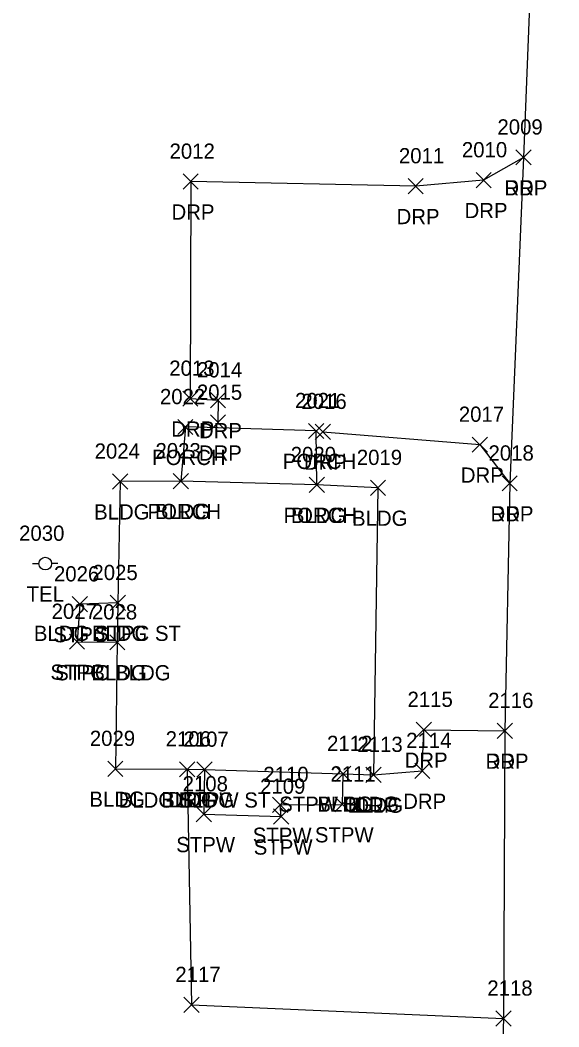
# Model space of a CAD drawing. Extents: x 1767353 to 1772625, y 740790 to 747702.
# Drawn here: x 1770195.4 to 1770266.1, y 741538.9 to 741671.2 of the extents above; entities that cross this region are included whole.
import ezdxf

# ---------------------------------------------------------------- set-up
doc = ezdxf.new("R2010")
doc.units = 0
for name, color, linetype in [('L_A', 7, 'Continuous'), ('L_I', 7, 'Continuous'), ('L_TIC', 7, 'Continuous'), ('LBC', 7, 'Continuous'), ('LBF', 7, 'Continuous'), ('P_A', 7, 'Continuous'), ('P_I', 7, 'Continuous'), ('P_TIC', 7, 'Continuous'), ('PET', 7, 'Continuous'), ('R_A', 7, 'Continuous'), ('R_I', 7, 'Continuous'), ('R_TIC', 7, 'Continuous'), ('RDP', 7, 'Continuous'), ('U_A', 7, 'Continuous'), ('U_I', 7, 'Continuous'), ('UP', 7, 'Continuous')]:
    doc.layers.add(name, color=color, linetype=linetype)

msp = doc.modelspace()

# ---------------------------------------------------------------- linework, layer by layer
at = {"layer": 'L_TIC'}
for points in [[(1770216.09, 741616.75), (1770218.09, 741618.75)], [(1770218.09, 741616.75), (1770216.09, 741618.75)], [(1770233.26, 741616.23), (1770235.26, 741618.23)], [(1770235.26, 741616.23), (1770233.26, 741618.23)], [(1770207.51, 741609.59), (1770209.51, 741611.59)], [(1770209.51, 741609.59), (1770207.51, 741611.59)], [(1770215.5, 741609.64), (1770217.5, 741611.64)], [(1770217.5, 741609.64), (1770215.5, 741611.64)], [(1770215.5, 741609.64), (1770217.5, 741611.64)], [(1770217.5, 741609.64), (1770215.5, 741611.64)], [(1770233.35, 741609.14), (1770235.35, 741611.14)], [(1770235.35, 741609.14), (1770233.35, 741611.14)], [(1770233.35, 741609.14), (1770235.35, 741611.14)], [(1770235.35, 741609.14), (1770233.35, 741611.14)], [(1770241.39, 741608.76), (1770243.39, 741610.76)], [(1770243.39, 741608.76), (1770241.39, 741610.76)], [(1770241.39, 741608.76), (1770243.39, 741610.76)], [(1770243.39, 741608.76), (1770241.39, 741610.76)], [(1770202.22, 741593.45), (1770204.22, 741595.45)], [(1770204.22, 741593.45), (1770202.22, 741595.45)], [(1770207.22, 741593.63), (1770209.22, 741595.63)], [(1770209.22, 741593.63), (1770207.22, 741595.63)], [(1770207.22, 741593.63), (1770209.22, 741595.63)], [(1770209.22, 741593.63), (1770207.22, 741595.63)], [(1770201.86, 741588.53), (1770203.86, 741590.53)], [(1770203.86, 741588.53), (1770201.86, 741590.53)], [(1770207.15, 741588.45), (1770209.15, 741590.45)], [(1770209.15, 741588.45), (1770207.15, 741590.45)], [(1770207.15, 741588.45), (1770209.15, 741590.45)], [(1770209.15, 741588.45), (1770207.15, 741590.45)], [(1770206.89, 741571.83), (1770208.89, 741573.83)], [(1770208.89, 741571.83), (1770206.89, 741573.83)], [(1770216.33, 741571.76), (1770218.33, 741573.76)], [(1770218.33, 741571.76), (1770216.33, 741573.76)], [(1770218.61, 741571.72), (1770220.61, 741573.72)], [(1770220.61, 741571.72), (1770218.61, 741573.72)], [(1770218.61, 741571.72), (1770220.61, 741573.72)], [(1770220.61, 741571.72), (1770218.61, 741573.72)], [(1770236.83, 741571.17), (1770238.83, 741573.17)], [(1770238.83, 741571.17), (1770236.83, 741573.17)], [(1770236.83, 741571.17), (1770238.83, 741573.17)], [(1770238.83, 741571.17), (1770236.83, 741573.17)], [(1770240.81, 741571.04), (1770242.81, 741573.04)], [(1770242.81, 741571.04), (1770240.81, 741573.04)], [(1770240.81, 741571.04), (1770242.81, 741573.04)], [(1770242.81, 741571.04), (1770240.81, 741573.04)], [(1770218.5, 741565.86), (1770220.5, 741567.86)], [(1770220.5, 741565.86), (1770218.5, 741567.86)], [(1770228.54, 741567.09), (1770230.54, 741569.09)], [(1770230.54, 741567.09), (1770228.54, 741569.09)], [(1770236.71, 741567.15), (1770238.71, 741569.15)], [(1770238.71, 741567.15), (1770236.71, 741569.15)], [(1770228.68, 741565.54), (1770230.68, 741567.54)], [(1770230.68, 741565.54), (1770228.68, 741567.54)]]:
    msp.add_lwpolyline(points, dxfattribs=at)
at = {"layer": 'LBC'}
for points in [[(1770242.39, 741609.76), (1770234.35, 741610.14), (1770216.5, 741610.64), (1770208.51, 741610.59), (1770208.22, 741594.63), (1770208.15, 741589.45), (1770207.89, 741572.83), (1770217.33, 741572.76), (1770219.61, 741572.72), (1770237.83, 741572.17), (1770241.81, 741572.04)], [(1770242.39, 741609.76), (1770241.81, 741572.04)]]:
    msp.add_lwpolyline(points, dxfattribs=at)
at = {"layer": 'LBF'}
for points in [[(1770234.35, 741610.14), (1770234.26, 741617.23), (1770217.09, 741617.75), (1770216.5, 741610.64)], [(1770208.22, 741594.63), (1770203.22, 741594.45), (1770202.86, 741589.53), (1770208.15, 741589.45)], [(1770219.61, 741572.72), (1770219.5, 741566.86), (1770229.68, 741566.54), (1770229.54, 741568.09), (1770237.71, 741568.15), (1770237.83, 741572.17)]]:
    msp.add_lwpolyline(points, dxfattribs=at)
at = {"layer": 'P_TIC'}
for points in [[(1770260.51, 741652.19), (1770262.51, 741654.19)], [(1770262.51, 741652.19), (1770260.51, 741654.19)], [(1770258.69, 741609.34), (1770260.69, 741611.34)], [(1770260.69, 741609.34), (1770258.69, 741611.34)], [(1770258.69, 741609.34), (1770260.69, 741611.34)], [(1770260.69, 741609.34), (1770258.69, 741611.34)], [(1770258.04, 741576.82), (1770260.04, 741578.82)], [(1770260.04, 741576.82), (1770258.04, 741578.82)], [(1770257.88, 741539.01), (1770259.88, 741541.01)], [(1770259.88, 741539.01), (1770257.88, 741541.01)]]:
    msp.add_lwpolyline(points, dxfattribs=at)
at = {"layer": 'PET'}
for points in [[(1770229.78, 741893.6), (1770250.07, 741887.1), (1770256.68, 741881.35), (1770263.49, 741873.94), (1770265.43, 741863.52), (1770266.15, 741845.69), (1770265.98, 741804.45), (1770264.31, 741748.35), (1770263.25, 741697.67), (1770261.51, 741653.19), (1770259.69, 741610.34)], [(1770259.69, 741610.34), (1770259.04, 741577.82), (1770258.88, 741540.01), (1770257.94, 741510.97), (1770256.82, 741408.89)]]:
    msp.add_lwpolyline(points, dxfattribs=at)
at = {"layer": 'R_TIC'}
for points in [[(1770260.51, 741652.19), (1770262.51, 741654.19)], [(1770262.51, 741652.19), (1770260.51, 741654.19)], [(1770216.79, 741649.01), (1770218.79, 741651.01)], [(1770218.79, 741649.01), (1770216.79, 741651.01)], [(1770246.34, 741648.41), (1770248.34, 741650.41)], [(1770248.34, 741648.41), (1770246.34, 741650.41)], [(1770255.27, 741649.2), (1770257.27, 741651.2)], [(1770257.27, 741649.2), (1770255.27, 741651.2)], [(1770216.74, 741620.48), (1770218.74, 741622.48)], [(1770218.74, 741620.48), (1770216.74, 741622.48)], [(1770220.38, 741620.27), (1770222.38, 741622.27)], [(1770222.38, 741620.27), (1770220.38, 741622.27)], [(1770220.37, 741617.33), (1770222.37, 741619.33)], [(1770222.37, 741617.33), (1770220.37, 741619.33)], [(1770234.16, 741616.12), (1770236.16, 741618.12)], [(1770236.16, 741616.12), (1770234.16, 741618.12)], [(1770254.78, 741614.43), (1770256.78, 741616.43)], [(1770256.78, 741614.43), (1770254.78, 741616.43)], [(1770258.69, 741609.34), (1770260.69, 741611.34)], [(1770260.69, 741609.34), (1770258.69, 741611.34)], [(1770247.4, 741576.96), (1770249.4, 741578.96)], [(1770249.4, 741576.96), (1770247.4, 741578.96)], [(1770258.04, 741576.82), (1770260.04, 741578.82)], [(1770260.04, 741576.82), (1770258.04, 741578.82)], [(1770216.33, 741571.76), (1770218.33, 741573.76)], [(1770218.33, 741571.76), (1770216.33, 741573.76)], [(1770247.21, 741571.56), (1770249.21, 741573.56)], [(1770249.21, 741571.56), (1770247.21, 741573.56)], [(1770240.81, 741571.04), (1770242.81, 741573.04)], [(1770242.81, 741571.04), (1770240.81, 741573.04)], [(1770216.9, 741540.8), (1770218.9, 741542.8)], [(1770218.9, 741540.8), (1770216.9, 741542.8)], [(1770257.88, 741539.01), (1770259.88, 741541.01)], [(1770259.88, 741539.01), (1770257.88, 741541.01)]]:
    msp.add_lwpolyline(points, dxfattribs=at)
at = {"layer": 'RDP'}
for points in [[(1770261.51, 741653.19), (1770256.27, 741650.2), (1770247.34, 741649.41), (1770217.79, 741650.01), (1770217.74, 741621.48), (1770221.38, 741621.27), (1770221.37, 741618.33)], [(1770235.16, 741617.12), (1770255.78, 741615.43), (1770259.69, 741610.34)], [(1770241.81, 741572.04), (1770248.21, 741572.56), (1770248.4, 741577.96), (1770259.04, 741577.82)], [(1770217.33, 741572.76), (1770217.9, 741541.8), (1770258.88, 741540.01)]]:
    msp.add_lwpolyline(points, dxfattribs=at)
at = {"layer": 'UP'}
for p, q in [((1770197.02, 741599.79), (1770197.84, 741599.79)), ((1770198.68, 741599.79), (1770198.68, 741599.79)), ((1770200.34, 741599.79), (1770199.51, 741599.79)), ((1770199.51, 741599.79), (1770199.51, 741599.79)), ((1770200.34, 741599.79), (1770200.34, 741599.79))]:
    msp.add_line(p, q, dxfattribs=at)
msp.add_circle((1770198.68, 741599.79), 0.833, dxfattribs=at)

# ---------------------------------------------------------------- texts
at = {"layer": 'L_A'}
for s, p in [('PORCH', (1770212.72, 741612.75)), ('PORCH', (1770229.88, 741612.23)), ('BLDG', (1770205.1, 741605.59)), ('PORCH', (1770212.12, 741605.64)), ('BLDG', (1770213.09, 741605.64)), ('PORCH', (1770229.98, 741605.14)), ('BLDG', (1770230.95, 741605.14)), ('BLDG', (1770238.98, 741604.76)), ('BLDG', (1770238.98, 741604.76)), ('BLDG STPC ST', (1770197.19, 741589.63)), ('STPC', (1770199.74, 741589.45)), ('BLDG', (1770204.81, 741589.63)), ('STPC', (1770199.37, 741584.53)), ('STPC BLDG', (1770199.99, 741584.45)), ('BLDG', (1770204.74, 741584.45)), ('BLDG', (1770204.48, 741567.83)), ('BLDG STPW ST', (1770208.33, 741567.72)), ('BLDG', (1770213.92, 741567.76)), ('BLDG', (1770216.2, 741567.72)), ('STPW BLDG', (1770229.41, 741567.17)), ('BLDG', (1770234.42, 741567.17)), ('BLDG', (1770238.4, 741567.04)), ('BLDG', (1770238.4, 741567.04)), ('STPW', (1770215.89, 741561.86)), ('STPW', (1770225.94, 741563.09)), ('STPW', (1770234.1, 741563.15)), ('STPW', (1770226.07, 741561.54))]:
    msp.add_text(s, height=2, dxfattribs=at).set_placement(p)
at = {"layer": 'L_I'}
for s, p in [('2022', (1770213.75, 741620.75)), ('2021', (1770231.49, 741620.23)), ('2024', (1770205.17, 741613.59)), ('2023', (1770213.16, 741613.64)), ('2023', (1770213.16, 741613.64)), ('2020', (1770230.93, 741613.14)), ('2020', (1770230.93, 741613.14)), ('2019', (1770239.61, 741612.76)), ('2019', (1770239.61, 741612.76)), ('2025', (1770204.88, 741597.63)), ('2025', (1770204.88, 741597.63)), ('2026', (1770199.83, 741597.45)), ('2027', (1770199.52, 741592.53)), ('2028', (1770204.81, 741592.45)), ('2028', (1770204.81, 741592.45)), ('2029', (1770204.54, 741575.83)), ('2106', (1770214.5, 741575.76)), ('2107', (1770216.84, 741575.72)), ('2107', (1770216.84, 741575.72)), ('2112', (1770235.7, 741575.17)), ('2112', (1770235.7, 741575.17)), ('2113', (1770239.69, 741575.04)), ('2113', (1770239.69, 741575.04)), ('2111', (1770236.15, 741571.15)), ('2108', (1770216.73, 741569.86)), ('2110', (1770227.33, 741571.09)), ('2109', (1770226.9, 741569.54))]:
    msp.add_text(s, height=2, dxfattribs=at).set_placement(p)
at = {"layer": 'P_A'}
for p in [(1770258.99, 741648.19), (1770257.17, 741605.34), (1770257.17, 741605.34), (1770256.52, 741572.82)]:
    msp.add_text('RDP', height=2, dxfattribs=at).set_placement(p)
at = {"layer": 'P_I'}
for s, p in [('2009', (1770258.08, 741656.19)), ('2018', (1770256.91, 741613.34)), ('2018', (1770256.91, 741613.34)), ('2116', (1770256.86, 741580.82)), ('2118', (1770256.75, 741543.01))]:
    msp.add_text(s, height=2, dxfattribs=at).set_placement(p)
at = {"layer": 'R_A'}
for p in [(1770258.99, 741648.19), (1770215.27, 741645.01), (1770244.83, 741644.41), (1770253.76, 741645.2), (1770215.23, 741616.48), (1770218.87, 741616.27), (1770218.86, 741613.33), (1770232.65, 741612.12), (1770253.27, 741610.43), (1770257.17, 741605.34), (1770245.89, 741572.96), (1770256.52, 741572.82), (1770214.81, 741567.76), (1770245.7, 741567.56), (1770239.3, 741567.04)]:
    msp.add_text('DRP', height=2, dxfattribs=at).set_placement(p)
at = {"layer": 'R_I'}
for s, p in [('2009', (1770258.08, 741656.19)), ('2010', (1770253.41, 741653.2)), ('2012', (1770215.01, 741653.01)), ('2011', (1770245.14, 741652.41)), ('2013', (1770214.97, 741624.48)), ('2014', (1770218.61, 741624.27)), ('2015', (1770218.6, 741621.33)), ('2016', (1770232.33, 741620.12)), ('2017', (1770253.01, 741618.43)), ('2018', (1770256.91, 741613.34)), ('2115', (1770246.27, 741580.96)), ('2116', (1770256.86, 741580.82)), ('2106', (1770214.5, 741575.76)), ('2114', (1770246.09, 741575.56)), ('2113', (1770239.69, 741575.04)), ('2117', (1770215.77, 741544.8)), ('2118', (1770256.75, 741543.01))]:
    msp.add_text(s, height=2, dxfattribs=at).set_placement(p)
at = {"layer": 'U_A'}
msp.add_text('TEL', height=2, dxfattribs=at).set_placement((1770196.24, 741594.79))
at = {"layer": 'U_I'}
msp.add_text('2030', height=2, dxfattribs=at).set_placement((1770195.25, 741602.79))

doc.saveas('drawing.dxf')
